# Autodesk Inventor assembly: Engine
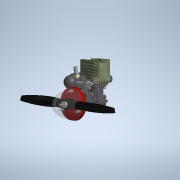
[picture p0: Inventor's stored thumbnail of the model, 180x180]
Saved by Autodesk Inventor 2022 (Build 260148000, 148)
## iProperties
Created: 2012-08
Part Number: Engine
Document SubType Name: Assembly
Designer: John
Author: John
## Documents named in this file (37)
- C:\Users\helfenj\Desktop\Ex_Files_Autodesk_Inventor_2022_Essential_Training\Exercise Files\03_Navigating the interface\03_03\Engine.iam
- C:\Users\helfenj\Desktop\Ex_Files_Autodesk_Inventor_2022_Essential_Training\Exercise Files\03_Navigating the interface\03_03\Engine Block.ipt
- C:\Users\helfenj\Desktop\Ex_Files_Autodesk_Inventor_2022_Essential_Training\Exercise Files\03_Navigating the interface\03_03\Crankshaft.ipt
- C:\Users\helfenj\Desktop\Ex_Files_Autodesk_Inventor_2022_Essential_Training\Exercise Files\03_Navigating the interface\03_03\Pulley Shaft.ipt
- C:\Users\helfenj\Desktop\Ex_Files_Autodesk_Inventor_2022_Essential_Training\Exercise Files\03_Navigating the interface\03_03\Sleeve.ipt
- C:\Users\helfenj\Desktop\Ex_Files_Autodesk_Inventor_2022_Essential_Training\Exercise Files\03_Navigating the interface\03_03\Piston Shaft.ipt
- C:\Users\helfenj\Desktop\Ex_Files_Autodesk_Inventor_2022_Essential_Training\Exercise Files\03_Navigating the interface\03_03\Piston.ipt
- C:\Users\helfenj\Desktop\Ex_Files_Autodesk_Inventor_2022_Essential_Training\Exercise Files\03_Navigating the interface\03_03\Piston Pin.ipt
- C:\Users\helfenj\Desktop\Ex_Files_Autodesk_Inventor_2022_Essential_Training\Exercise Files\03_Navigating the interface\03_03\Crank Arm.ipt
- C:\Users\helfenj\Desktop\Ex_Files_Autodesk_Inventor_2022_Essential_Training\Exercise Files\03_Navigating the interface\03_03\Face Plate.ipt
- C:\Users\helfenj\Desktop\Ex_Files_Autodesk_Inventor_2022_Essential_Training\Exercise Files\03_Navigating the interface\03_03\washer4.ipt
- C:\Users\helfenj\Desktop\Ex_Files_Autodesk_Inventor_2022_Essential_Training\Exercise Files\03_Navigating the interface\03_03\Screw Lock.ipt
- C:\Users\helfenj\Desktop\Ex_Files_Autodesk_Inventor_2022_Essential_Training\Exercise Files\03_Navigating the interface\03_03\Beveled Sleeve.ipt
- C:\Users\helfenj\Desktop\Ex_Files_Autodesk_Inventor_2022_Essential_Training\Exercise Files\03_Navigating the interface\03_03\Clutch Housing.ipt
- C:\Users\helfenj\Desktop\Ex_Files_Autodesk_Inventor_2022_Essential_Training\Exercise Files\03_Navigating the interface\03_03\Brake Pad.ipt
- C:\Users\helfenj\Desktop\Ex_Files_Autodesk_Inventor_2022_Essential_Training\Exercise Files\03_Navigating the interface\03_03\Clutch Sleeve14.ipt
- C:\Users\helfenj\Desktop\Ex_Files_Autodesk_Inventor_2022_Essential_Training\Exercise Files\03_Navigating the interface\03_03\Clutch Bearing.ipt
- C:\Users\helfenj\Desktop\Ex_Files_Autodesk_Inventor_2022_Essential_Training\Exercise Files\03_Navigating the interface\03_03\Clutch Sleeve11.ipt
- C:\Users\helfenj\Desktop\Ex_Files_Autodesk_Inventor_2022_Essential_Training\Exercise Files\03_Navigating the interface\03_03\Carburetor.iam
- C:\Users\helfenj\Desktop\Ex_Files_Autodesk_Inventor_2022_Essential_Training\Exercise Files\03_Navigating the interface\03_03\Heat Sink.ipt
- C:\Users\helfenj\Desktop\Ex_Files_Autodesk_Inventor_2022_Essential_Training\Exercise Files\03_Navigating the interface\03_03\Starter Cover.ipt
- C:\Users\helfenj\Desktop\Ex_Files_Autodesk_Inventor_2022_Essential_Training\Exercise Files\03_Navigating the interface\03_03\Horseshoe Clip.ipt
- C:\Users\helfenj\Desktop\Ex_Files_Autodesk_Inventor_2022_Essential_Training\Exercise Files\03_Navigating the interface\03_03\ANSI B18.3 - 3-48 UNC - 0.375(31).ipt
- C:\Users\helfenj\Desktop\Ex_Files_Autodesk_Inventor_2022_Essential_Training\Exercise Files\03_Navigating the interface\03_03\ANSI B18.3 - 2-56 UNC - 0.375(31).ipt
- C:\Users\helfenj\Desktop\Ex_Files_Autodesk_Inventor_2022_Essential_Training\Exercise Files\03_Navigating the interface\03_03\Muffler.ipt
- C:\Users\helfenj\Desktop\Ex_Files_Autodesk_Inventor_2022_Essential_Training\Exercise Files\03_Navigating the interface\03_03\ANSI B18.3 - 4-40 UNC - 0.875(31).ipt
- C:\Users\helfenj\Desktop\Ex_Files_Autodesk_Inventor_2022_Essential_Training\Exercise Files\03_Navigating the interface\03_03\Muffler Tip.ipt
- C:\Users\helfenj\Desktop\Ex_Files_Autodesk_Inventor_2022_Essential_Training\Exercise Files\03_Navigating the interface\03_03\Starter Handle.ipt
- C:\Users\helfenj\Desktop\Ex_Files_Autodesk_Inventor_2022_Essential_Training\Exercise Files\03_Navigating the interface\03_03\ANSI B18.3 - 1-64 UNC - UNC - 0.25(1).ipt
- C:\Users\helfenj\Desktop\Ex_Files_Autodesk_Inventor_2022_Essential_Training\Exercise Files\03_Navigating the interface\03_03\Clutch Prop Mount.ipt
- C:\Users\helfenj\Desktop\Ex_Files_Autodesk_Inventor_2022_Essential_Training\Exercise Files\03_Navigating the interface\03_03\Prop Mount.ipt
- C:\Users\helfenj\Desktop\Ex_Files_Autodesk_Inventor_2022_Essential_Training\Exercise Files\03_Navigating the interface\03_03\Prop.ipt
- C:\Users\helfenj\Desktop\Ex_Files_Autodesk_Inventor_2022_Essential_Training\Exercise Files\03_Navigating the interface\03_03\Cone.ipt
- C:\Users\helfenj\Desktop\Ex_Files_Autodesk_Inventor_2022_Essential_Training\Exercise Files\03_Navigating the interface\03_03\Crankshaft Cover.ipt
- C:\Users\helfenj\Desktop\Ex_Files_Autodesk_Inventor_2022_Essential_Training\Exercise Files\03_Navigating the interface\03_03\ANSI B18.3 - 10-24 UNC - UNC - 0.5(1).ipt
- C:\Users\helfenj\Desktop\Ex_Files_Autodesk_Inventor_2022_Essential_Training\Exercise Files\03_Navigating the interface\03_03\ANSI B18.2.2 - 1_4 - 20(3).ipt
- C:\Users\helfenj\Desktop\Ex_Files_Autodesk_Inventor_2022_Essential_Training\Exercise Files\03_Navigating the interface\03_03\ASME B18.21.1 - No. 10. Carbon Steel(4).ipt
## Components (50 placed, 36 different names)
1. Engine Block:1 — Mate:1, Mate:2, Insert:1, Mate:8, Insert:2, Mate:16, Mate:21, Flush:1, Mate:42, Angle:1, Mate:43, Mate:47, Mate:49, Mate:50, Mate:51, Mate:57, Mate:58, Mate:59, Flush:3
2. Crankshaft:1 — Mate:1, Mate:2, Mate:3, Mate:4, Mate:11, Mate:13, Mate:23, Mate:24, Mate:25, Angle:6, DRIVE THIS
3. Pulley Shaft:1 — Mate:3, Mate:4, Mate:7, Mate:17, Mate:18, Mate:19
4. Sleeve:1 — Mate:7, Mate:20
5. Piston Shaft:1 — Insert:1, Mate:8, Mate:12, Mate:48
6. Piston:1 — Mate:10, Mate:12, Mate:14, Mate:15
7. Piston Pin:1 — Mate:9, Mate:10, Mate:14, Mate:15
8. Crank Arm:1 — Mate:9, Mate:11, Mate:13
9. Face Plate:1 — Insert:2, Mate:16, Mate:17, Mate:52, Mate:60, Mate:61, DRIVE THIS
10. washer4:1 — Mate:18, Mate:19, Mate:20
11. Screw Lock:1 — Mate:21, Flush:1
12. Beveled Sleeve:1 — Mate:23, Flush:2
13. Clutch Housing:1 — Mate:24, Flush:2, Mate:27, Mate:29, Mate:30, Mate:31, Mate:32, Mate:47
14. Brake Pad:1 — Mate:31, Mate:32, Tangent:2
15. Brake Pad:2 — Mate:29, Mate:30, Tangent:1, Mate:41
16. Clutch Sleeve14:1 — Mate:25, Mate:27, Mate:33, Mate:34, Mate:37, Mate:39, Mate:53, Mate:54
17. Clutch Bearing:1 — Mate:33, Mate:35
18. Clutch Prop Mount:1 — Mate:34, Mate:35, Tangent:1, Tangent:2, Mate:38, Mate:41, Mate:62, Mate:63, Mate:68
19. Clutch Bearing:2 — Mate:37, Mate:38, Mate:40
20. Clutch Sleeve11:1 — Mate:39, Mate:40
21. Carburetor:1 [sub-assembly] — Mate:42, Angle:1, Mate:43
22. Heat Sink:1 — Mate:48, Mate:49, Mate:50, Mate:51
23. Starter Cover:1 — Mate:52, Mate:60, Mate:61, Insert:13
24. Horseshoe Clip:1 — Mate:53, Mate:54
25. Muffler Tip:1 — Mate:55, Angle:2, Mate:56
26. Muffler:1 — Mate:55, Angle:2, Mate:56, Mate:57, Mate:58, Mate:59
27. Starter Handle:1 — Insert:13
28. Hexagon Socket Head Cap Screw - Inch No. 3 - 48 UNC - 3/8:1
29. Hexagon Socket Head Cap Screw - Inch No. 3 - 48 UNC - 3/8:2
30. Hexagon Socket Head Cap Screw - Inch No. 3 - 48 UNC - 3/8:3
31. Hexagon Socket Head Cap Screw - Inch No. 3 - 48 UNC - 3/8:4
32. Hexagon Socket Head Cap Screw - Inch No. 2 - 56 UNC - 3/8:1
33. Hexagon Socket Head Cap Screw - Inch No. 2 - 56 UNC - 3/8:2
34. Hexagon Socket Head Cap Screw - Inch No. 2 - 56 UNC - 3/8:3
35. Hexagon Socket Head Cap Screw - Inch No. 2 - 56 UNC - 3/8:4
36. Hexagon Socket Head Cap Screw - Inch No. 4 - 40 UNC - 7/8:1
37. Hexagon Socket Head Cap Screw - Inch No. 4 - 40 UNC - 7/8:2
38. Hexagon Socket Button Head Cap Screw - Inch 1 - 64 x 1/4:1
39. Hexagon Socket Button Head Cap Screw - Inch 1 - 64 x 1/4:2
40. Hexagon Socket Button Head Cap Screw - Inch 1 - 64 x 1/4:3
41. Hexagon Socket Button Head Cap Screw - Inch 1 - 64 x 1/4:4
42. Prop Mount:1 — Mate:62, Mate:63, Mate:64, Mate:65, Mate:66, Mate:67, Angle:4
43. Prop:1 — Mate:64, Mate:65, Angle:4, Mate:68, Angle:5, Angle:6
44. Cone:1 — Mate:66, Mate:67, Angle:5
45. Crankshaft Cover:1 — Flush:3
46. Hexagon Socket Button Head Cap Screw - Inch 10 - 24 x 1/2:1
47. Hexagon Socket Button Head Cap Screw - Inch 10 - 24 x 1/2:2
48. Hexagon Socket Button Head Cap Screw - Inch 10 - 24 x 1/2:3
49. External Tooth Lock Washer - Type A (Inch) No. 10. Carbon Steel:1 — Mate:70
50. Hex Jam Nut - Inch 1/4 - 20:1 — Mate:70
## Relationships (74: Mate 60, Angle 6, Insert 3, Flush 3, Tangent 2)
- Mate:1: Engine Block:1 ↔ Crankshaft:1
- Mate:2: Engine Block:1 ↔ Crankshaft:1
- Mate:3: Crankshaft:1 ↔ Pulley Shaft:1
- Mate:4: Crankshaft:1 ↔ Pulley Shaft:1
- Mate:7: Pulley Shaft:1 ↔ Sleeve:1
- Insert:1: Engine Block:1 ↔ Piston Shaft:1
- Mate:8: Engine Block:1 ↔ Piston Shaft:1
- Mate:9: Piston Pin:1 ↔ Crank Arm:1
- Mate:10: Piston:1 ↔ Piston Pin:1
- Mate:11: Crankshaft:1 ↔ Crank Arm:1
- Mate:12: Piston Shaft:1 ↔ Piston:1
- Mate:13: Crankshaft:1 ↔ Crank Arm:1
- Mate:14: Piston:1 ↔ Piston Pin:1
- Mate:15: Piston:1 ↔ Piston Pin:1
- Insert:2: Engine Block:1 ↔ Face Plate:1
- Mate:16: Engine Block:1 ↔ Face Plate:1
- Mate:17: Pulley Shaft:1 ↔ Face Plate:1
- Mate:18: Pulley Shaft:1 ↔ washer4:1
- Mate:19: Pulley Shaft:1 ↔ washer4:1
- Mate:20: Sleeve:1 ↔ washer4:1
- Mate:21: Engine Block:1 ↔ Screw Lock:1
- Flush:1: Engine Block:1 ↔ Screw Lock:1
- Mate:23: Crankshaft:1 ↔ Beveled Sleeve:1
- Mate:24: Crankshaft:1 ↔ Clutch Housing:1
- Flush:2: Beveled Sleeve:1 ↔ Clutch Housing:1
- Mate:25: Crankshaft:1 ↔ Clutch Sleeve14:1
- Mate:27: Clutch Housing:1 ↔ Clutch Sleeve14:1
- Mate:29: Clutch Housing:1 ↔ Brake Pad:2
- Mate:30: Clutch Housing:1 ↔ Brake Pad:2
- Mate:31: Clutch Housing:1 ↔ Brake Pad:1
- Mate:32: Clutch Housing:1 ↔ Brake Pad:1
- Mate:33: Clutch Sleeve14:1 ↔ Clutch Bearing:1
- Mate:34: Clutch Sleeve14:1 ↔ Clutch Prop Mount:1
- Mate:35: Clutch Bearing:1 ↔ Clutch Prop Mount:1
- Tangent:1: Brake Pad:2 ↔ Clutch Prop Mount:1
- Tangent:2: Brake Pad:1 ↔ Clutch Prop Mount:1
- Mate:37: Clutch Sleeve14:1 ↔ Clutch Bearing:2
- Mate:38: Clutch Prop Mount:1 ↔ Clutch Bearing:2
- Mate:39: Clutch Sleeve14:1 ↔ Clutch Sleeve11:1
- Mate:40: Clutch Bearing:2 ↔ Clutch Sleeve11:1
- Mate:41: Brake Pad:2 ↔ Clutch Prop Mount:1
- Mate:42: Engine Block:1 ↔ Carburetor:1
- Angle:1: Engine Block:1 ↔ Carburetor:1
- Mate:43: Engine Block:1 ↔ Carburetor:1
- Mate:47: Engine Block:1 ↔ Clutch Housing:1
- Mate:48: Piston Shaft:1 ↔ Heat Sink:1
- Mate:49: Engine Block:1 ↔ Heat Sink:1
- Mate:50: Engine Block:1 ↔ Heat Sink:1
- Mate:51: Engine Block:1 ↔ Heat Sink:1
- Mate:52: Face Plate:1 ↔ Starter Cover:1
- Mate:53: Clutch Sleeve14:1 ↔ Horseshoe Clip:1
- Mate:54: Clutch Sleeve14:1 ↔ Horseshoe Clip:1
- Mate:55: Muffler Tip:1 ↔ Muffler:1
- Angle:2: Muffler Tip:1 ↔ Muffler:1
- Mate:56: Muffler Tip:1 ↔ Muffler:1
- Mate:57: Engine Block:1 ↔ Muffler:1
- Mate:58: Engine Block:1 ↔ Muffler:1
- Mate:59: Engine Block:1 ↔ Muffler:1
- Mate:60: Face Plate:1 ↔ Starter Cover:1
- Mate:61: Face Plate:1 ↔ Starter Cover:1
- Insert:13: Starter Cover:1 ↔ Starter Handle:1
- Angle:6: Crankshaft:1 ↔ Prop:1
- DRIVE THIS [Angle]: Crankshaft:1 ↔ Face Plate:1
- Mate:62: Clutch Prop Mount:1 ↔ Prop Mount:1
- Mate:63: Clutch Prop Mount:1 ↔ Prop Mount:1
- Mate:64: Prop Mount:1 ↔ Prop:1
- Mate:65: Prop Mount:1 ↔ Prop:1
- Mate:66: Prop Mount:1 ↔ Cone:1
- Mate:67: Prop Mount:1 ↔ Cone:1
- Angle:4: Prop Mount:1 ↔ Prop:1
- Mate:68: Clutch Prop Mount:1 ↔ Prop:1
- Angle:5: Prop:1 ↔ Cone:1
- Flush:3: Engine Block:1 ↔ Crankshaft Cover:1
- Mate:70: External Tooth Lock Washer - Type A (Inch) No. 10. Carbon Steel:1 ↔ Hex Jam Nut - Inch 1/4 - 20:1
